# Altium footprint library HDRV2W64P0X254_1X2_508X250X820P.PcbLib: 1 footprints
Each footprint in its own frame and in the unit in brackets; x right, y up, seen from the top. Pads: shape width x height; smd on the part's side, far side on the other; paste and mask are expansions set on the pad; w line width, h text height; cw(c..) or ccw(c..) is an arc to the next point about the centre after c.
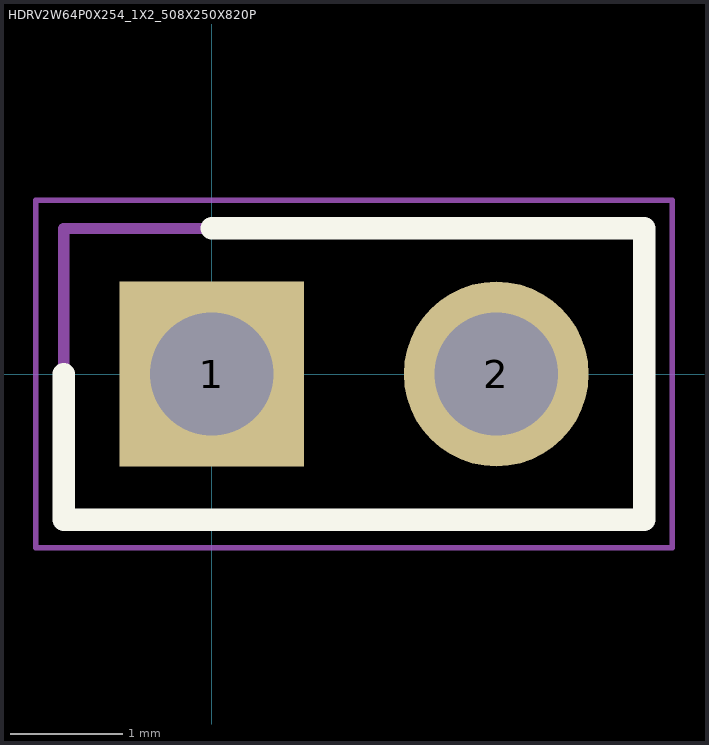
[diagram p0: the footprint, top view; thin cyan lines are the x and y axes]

## HDRV2W64P0X254_1X2_508X250X820P [mm]
pads (2):
  rect 1.65x1.65 / inner round 1.65 / far side rect 1.65x1.65 hole 1.1: 1(0,0)
  round 1.65 hole 1.1: 2(2.54,0)
Top Overlay:
  lines w0.2: -1.32,0 -1.32,-1.3 3.86,-1.3 3.86,1.3 0,1.3
Mechanical 15:
  lines w0.1: -1.32,-1.3 -1.32,1.3 3.86,1.3 3.86,-1.3 -1.32,-1.3
Mechanical 20:
  lines w0.05: -1.57,-1.55 -1.57,1.55 4.11,1.55 4.11,-1.55 -1.57,-1.55
3D body "961102-6404-AR.stp": height 5.8, standoff -4.65, extent -10,-3.376 10,3.376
